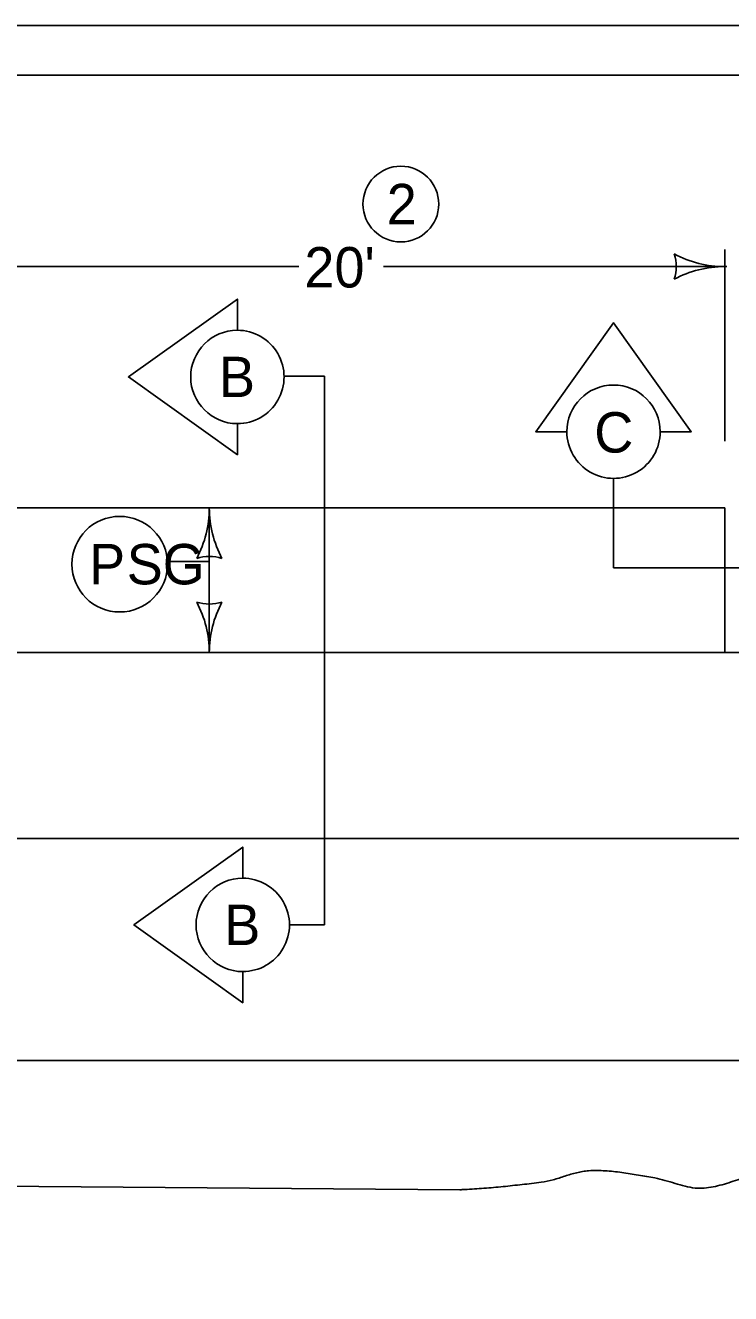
# Model space of a CAD drawing. Extents: x 10133 to 81668, y 7924 to 12229.
# Drawn here: x 11528 to 11808, y 9442 to 9944 of the extents above; entities that cross this region are included whole.
import ezdxf

# ---------------------------------------------------------------- set-up
doc = ezdxf.new("R2010")
doc.units = 0
for name, color, linetype in [('dsnTextFinalPlan', 7, 'Continuous'), ('Level 1', 7, 'Continuous'), ('Level 12', 7, 'Continuous'), ('Level 4', 7, 'Continuous'), ('Level 5', 7, 'Continuous'), ('Level 7', 7, 'Continuous'), ('SheetBorder', 7, 'Continuous')]:
    doc.layers.add(name, color=color, linetype=linetype)

msp = doc.modelspace()

# ---------------------------------------------------------------- linework, layer by layer
at = {"layer": 'dsnTextFinalPlan'}
for p, q in [((11739.87, 9783.03), (11730.63, 9783.11)), ((11737.24, 9783.05), (11730.63, 9783.11)), ((11805.49, 9752.95), (11500.75, 9752.95)), ((11805.49, 9752.95), (11805.49, 9695.63)), ((10368.64, 9695.63), (11982.35, 9695.63)), ((10368.86, 9622), (11982.65, 9622)), ((11371.34, 9485.38), (11700.54, 9482.92))]:
    msp.add_line(p, q, dxfattribs=at)
msp.add_spline([(11700.54, 9482.92), (11702.54, 9483.03), (11710.11, 9483.51), (11717.68, 9484.17), (11725.23, 9484.98), (11732.76, 9485.88), (11737.51, 9486.88), (11742.19, 9488.32), (11746.86, 9489.68), (11749.21, 9490.17), (11751.58, 9490.44), (11758.12, 9490.43), (11764.71, 9489.77), (11771.29, 9488.74), (11777.81, 9487.59), (11781.82, 9486.65), (11785.79, 9485.45), (11789.77, 9484.32), (11793.78, 9483.6), (11797.32, 9483.57), (11800.87, 9484.07), (11807.98, 9486), (11815.12, 9488.01), (11822.29, 9488.73), (11836.82, 9487.76), (11851.37, 9486.45), (11858.09, 9485.63), (11864.79, 9484.64), (11871.49, 9483.7), (11878.17, 9483.03), (11883.92, 9483.59), (11889.6, 9485.42), (11895.26, 9487.47), (11900.98, 9488.73), (11908.48, 9489.24), (11916.08, 9489.37), (11927.47, 9488.67), (11931.2, 9488.16), (11938.22, 9486.34), (11945.12, 9483.78), (11952.04, 9481.41), (11959.14, 9480.18), (11980.25, 9479.17)], degree=3, dxfattribs=at)
at = {"layer": 'Level 1'}
msp.add_line((10152.18, 9924.36), (13247.87, 9924.36), dxfattribs=at)
at = {"layer": 'Level 12'}
msp.add_circle((11677.2, 9873.25), 15, dxfattribs=at)
at = {"layer": 'Level 4'}
msp.add_line((10352.26, 9534.09), (11994.29, 9534.09), dxfattribs=at)
at = {"layer": 'Level 5'}
for p, q in [((11805.49, 9779.31), (11805.49, 9855.32)), ((11500.75, 9848.49), (11636.75, 9848.49)), ((11670.27, 9848.49), (11806.27, 9848.49)), ((11805.49, 9752.95), (11500.75, 9752.95)), ((11601.33, 9752.95), (11601.33, 9695.63)), ((11805.49, 9695.63), (11805.49, 9752.95)), ((11584.76, 9731.77), (11601.33, 9731.77)), ((10773.8, 9695.63), (11805.49, 9695.63))]:
    msp.add_line(p, q, dxfattribs=at)
msp.add_circle((11565.83, 9730.65), 18.93, dxfattribs=at)
msp.add_circle((11565.83, 9730.65), 18.93, dxfattribs=at)
for centre, radius, start, end in [((11769.86, 9848.49), 16.42, 342.2666, 17.7333), ((11805.49, 9890.99), 42.5, 241.9275, 270), ((11805.49, 9805.99), 42.5, 90, 118.0725), ((11558.83, 9752.95), 42.5, 331.9275, 0), ((11643.83, 9752.95), 42.5, 180, 208.0725), ((11601.33, 9717.31), 16.42, 72.2666, 107.7334), ((11601.33, 9731.27), 16.42, 252.2666, 287.7333), ((11558.83, 9695.63), 42.5, 360, 28.0725), ((11643.83, 9695.63), 42.5, 151.9275, 180)]:
    msp.add_arc(centre, radius, start, end, dxfattribs=at)
at = {"layer": 'Level 7'}
for p, q in [((11647.01, 9805.1), (11631.23, 9805.1)), ((11647.01, 9587.81), (11647.01, 9805.1)), ((11761.44, 9729.18), (11761.44, 9764.62)), ((11761.44, 9729.18), (11849.54, 9729.18)), ((11647.01, 9587.81), (11633.05, 9587.81))]:
    msp.add_line(p, q, dxfattribs=at)
for points in [[(11612.44, 9823.28), (11612.44, 9835.61), (11569.31, 9804.8), (11612.44, 9773.99), (11612.44, 9786.31)], [(11742.96, 9783.11), (11730.63, 9783.11), (11761.44, 9826.24), (11792.25, 9783.11), (11779.93, 9783.11)], [(11614.57, 9606.3), (11614.57, 9618.62), (11571.43, 9587.81), (11614.57, 9557), (11614.57, 9569.33)]]:
    msp.add_lwpolyline(points, dxfattribs=at)
for centre, start, end in [((11612.44, 9804.8), 90.0008, 269.9992), ((11612.44, 9804.8), 269.9992, 90.0008), ((11761.44, 9783.11), 0.0008, 179.9992), ((11761.44, 9783.11), 179.9992, 0.0008), ((11614.57, 9587.81), 90.0008, 269.9992), ((11614.57, 9587.81), 269.9992, 90.0008)]:
    msp.add_arc(centre, 18.49, start, end, dxfattribs=at)
at = {"layer": 'SheetBorder'}
msp.add_lwpolyline([(10132.52, 9944.02), (13267.53, 9944.02), (13267.53, 7924.02), (10132.52, 7924.02)], close=True, dxfattribs=at)

# ---------------------------------------------------------------- texts
at = {"layer": 'Level 12'}
msp.add_text('2', height=16, dxfattribs=at).set_placement((11671.62, 9865.25))
at = {"layer": 'Level 5'}
for s, p in [("20'", (11638.99, 9840.22)), ('P', (11553.7, 9722.65)), ('SG', (11568.61, 9722.65))]:
    msp.add_text(s, height=16, dxfattribs=at).set_placement(p)
at = {"layer": 'Level 7'}
for s, p in [('B', (11605.17, 9796.8)), ('C', (11753.81, 9774.84)), ('B', (11607.26, 9579.81))]:
    msp.add_text(s, height=16, dxfattribs=at).set_placement(p)

doc.saveas('drawing.dxf')
